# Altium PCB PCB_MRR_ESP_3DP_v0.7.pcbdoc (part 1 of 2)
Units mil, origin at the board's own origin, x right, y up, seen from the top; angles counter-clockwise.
Board outline 5100 x 5040 mil, 2 copper layers (Top Layer, Bottom Layer); 131 components, 154 nets, 480 pads, 79 vias.
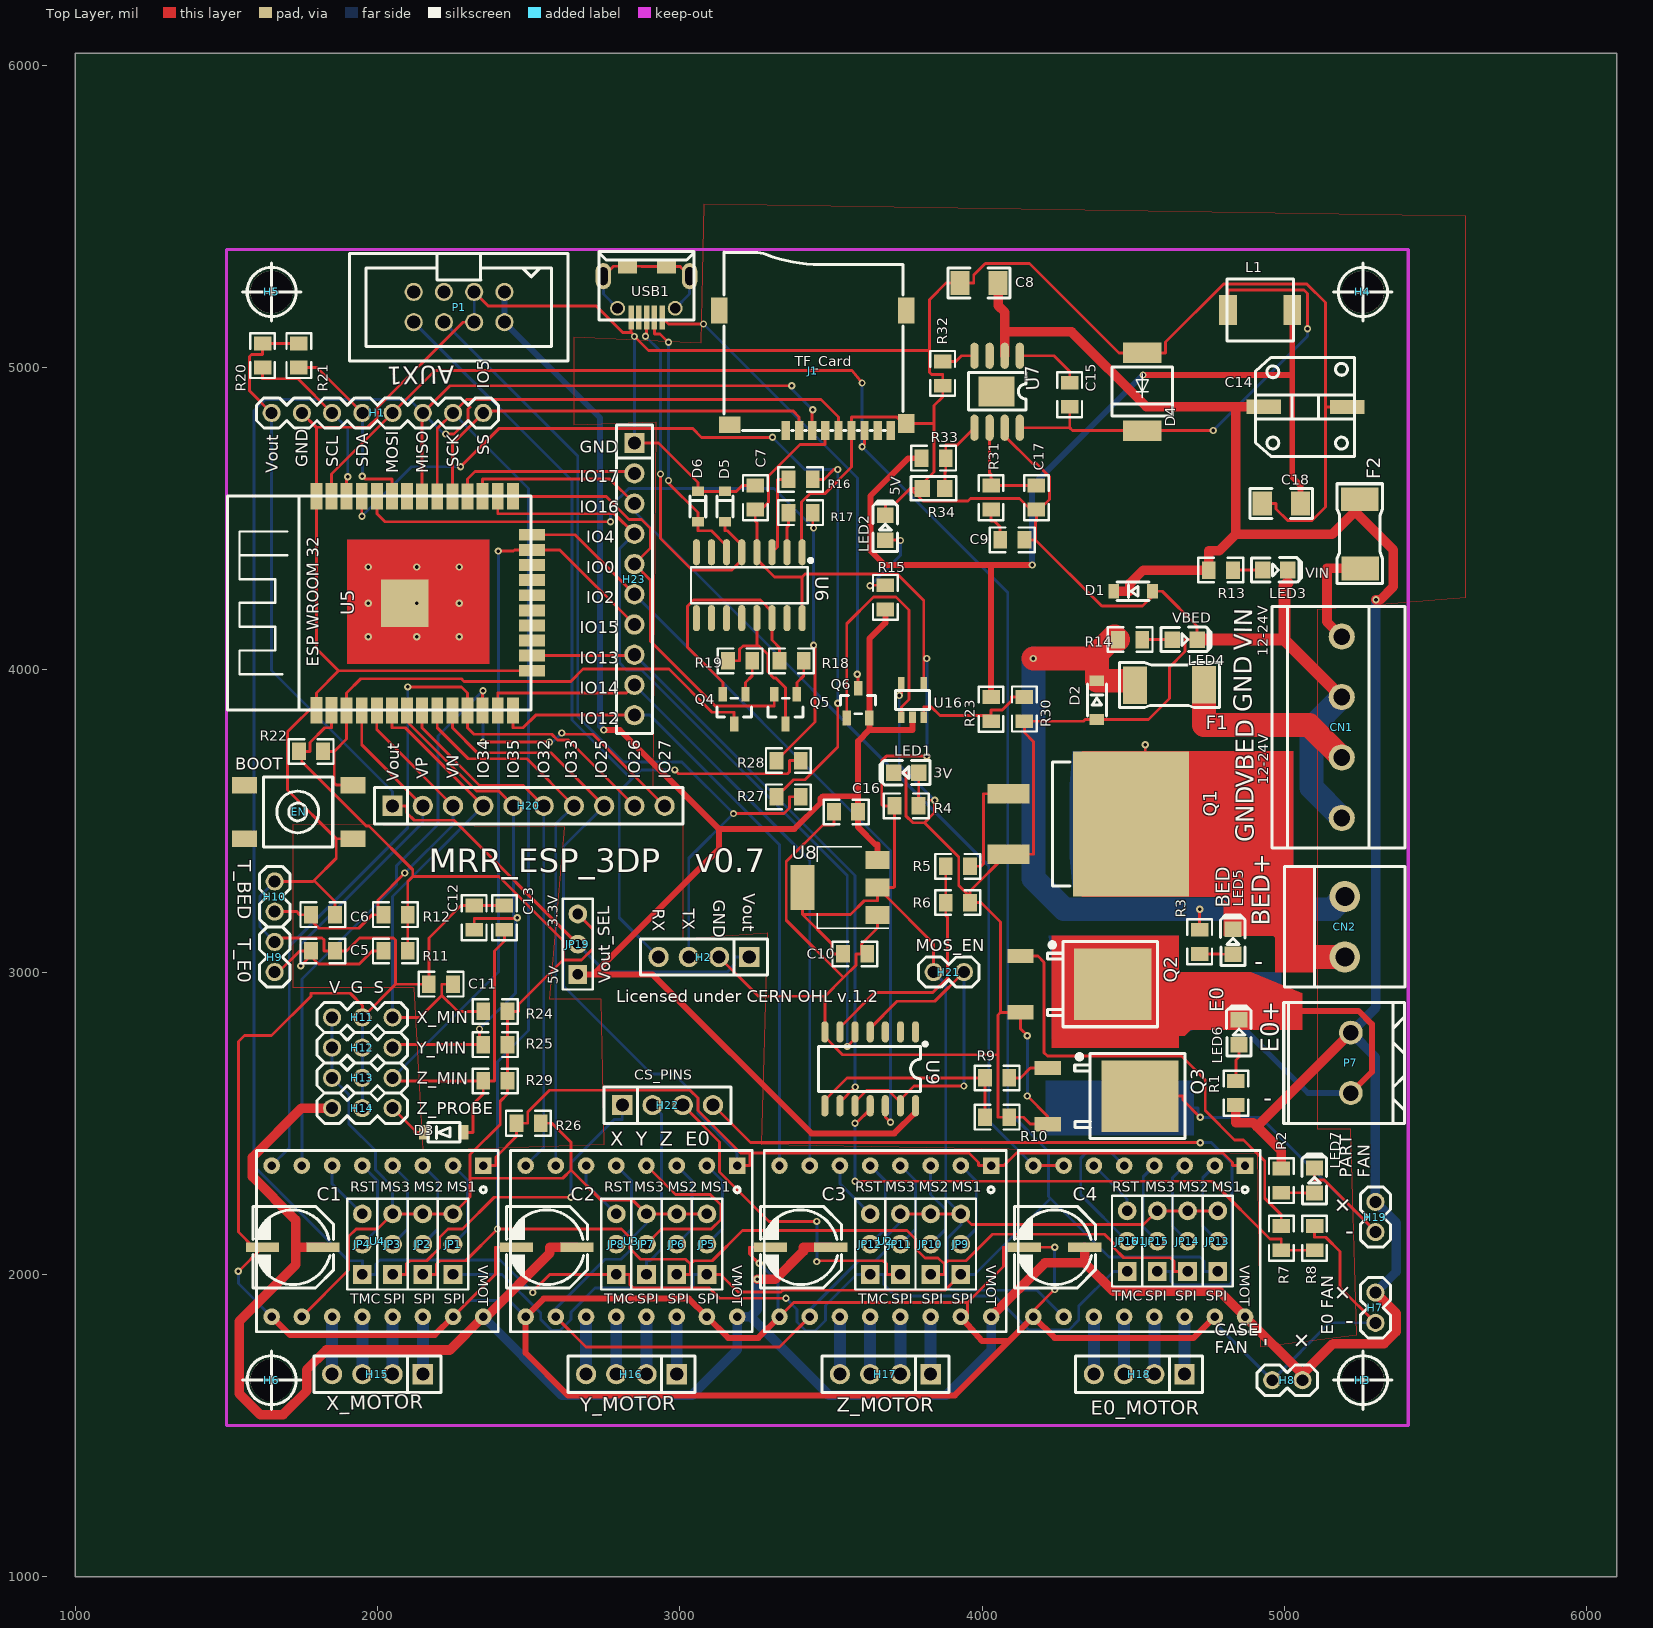
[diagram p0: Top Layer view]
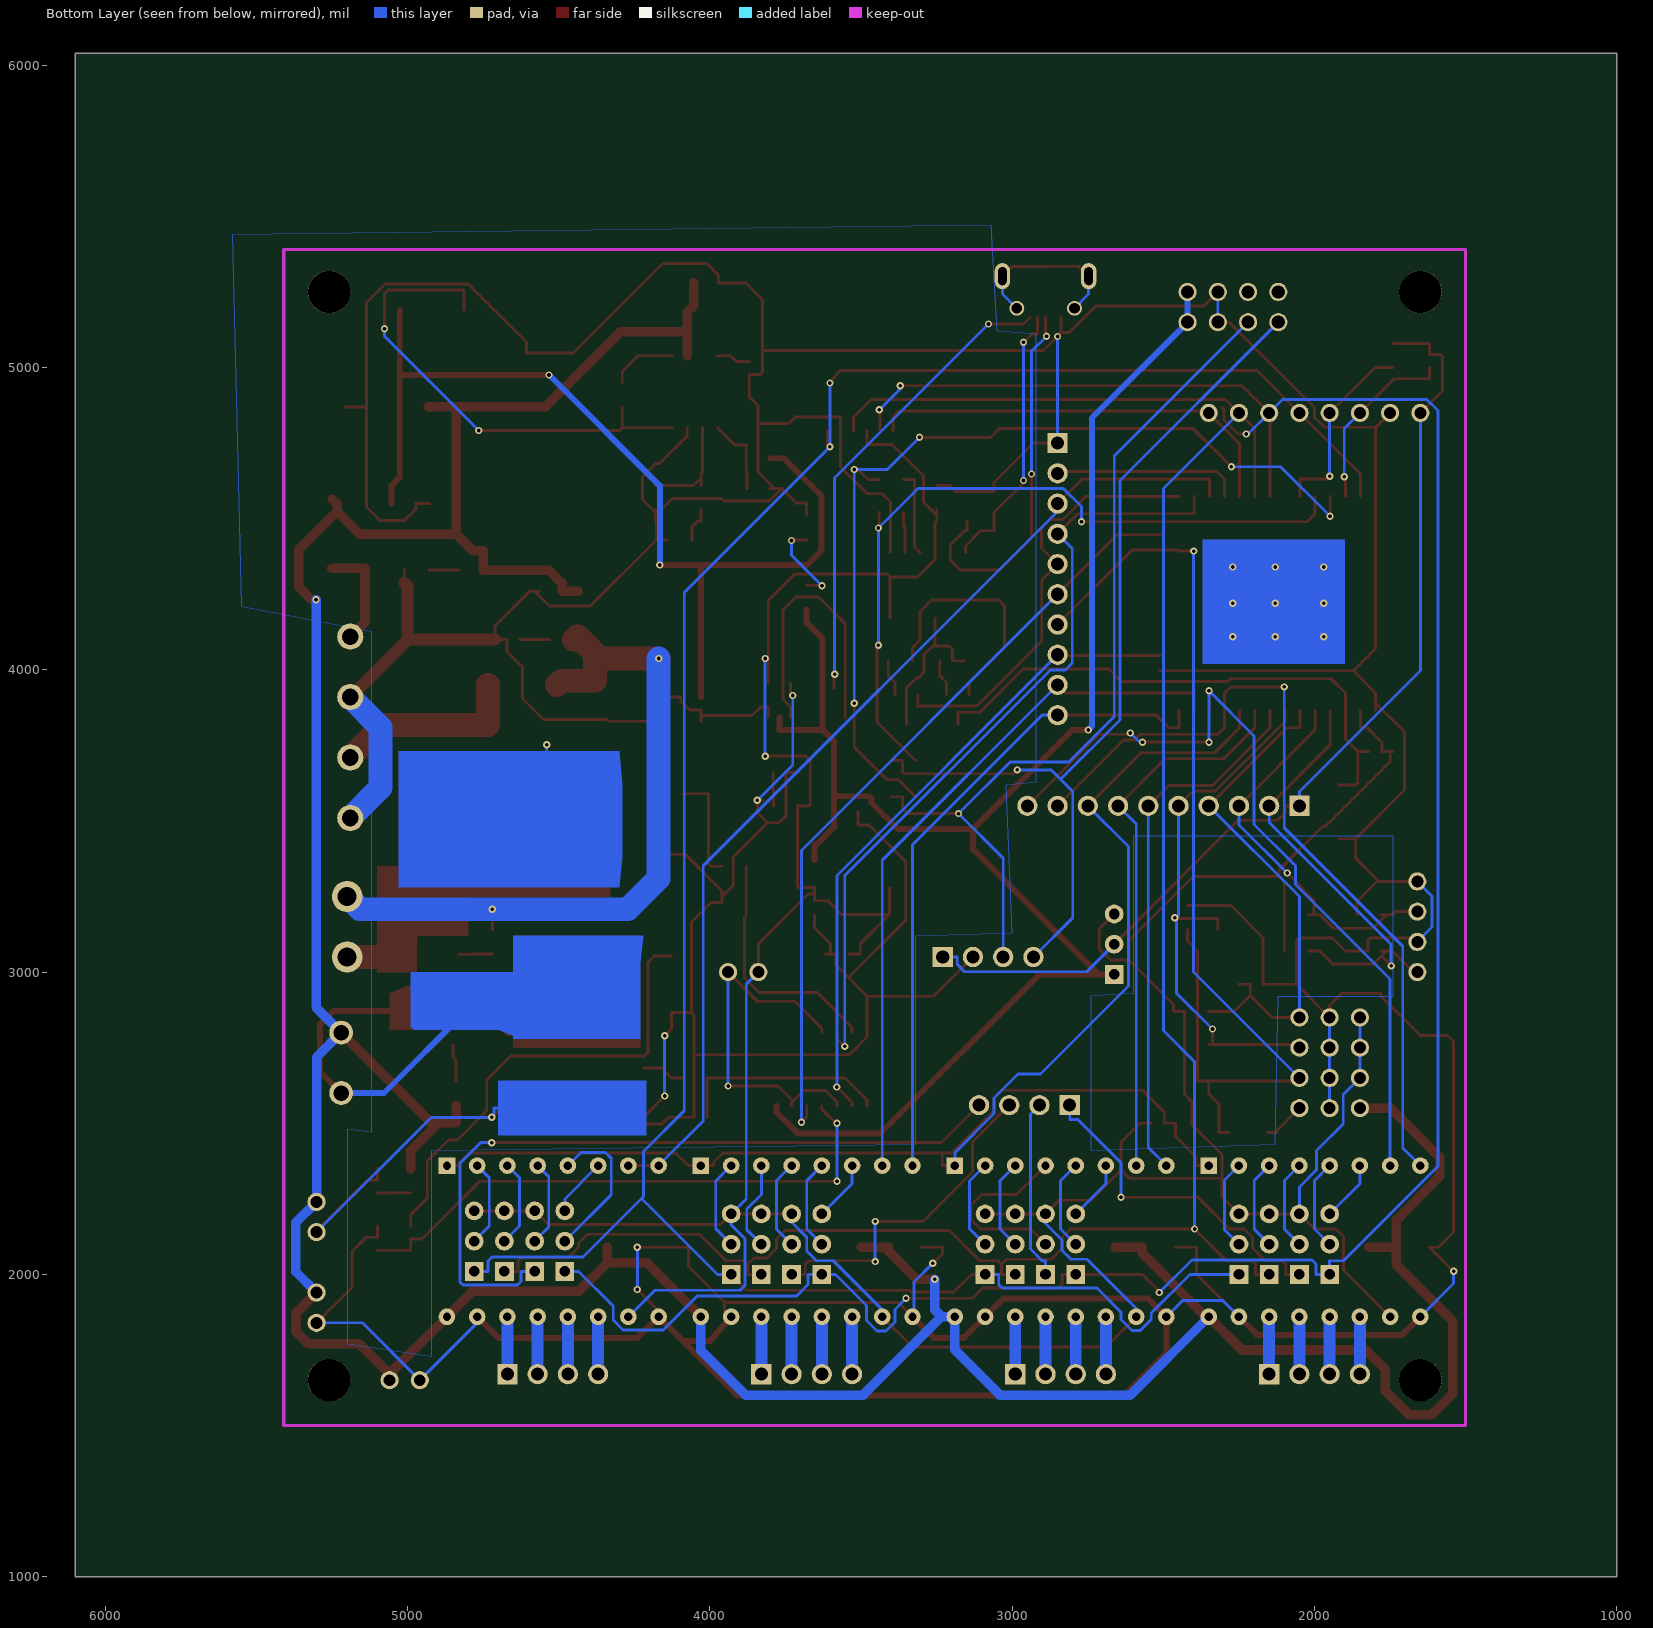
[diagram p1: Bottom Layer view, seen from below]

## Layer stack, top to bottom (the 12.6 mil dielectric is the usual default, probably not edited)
Top Layer: signal copper (thickness not stored)
Dielectric: dielectric 12.6, FR-4, Dk 4.8
Bottom Layer: signal copper (thickness not stored)

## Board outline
6100,1000 1000,1000 1000,6040 6100,6040

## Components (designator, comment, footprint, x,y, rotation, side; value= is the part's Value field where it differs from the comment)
C1 "100uF" CAP-D6.3XH7.7 1720,2090 r0 top
C2 "100uF" CAP-D6.3XH7.7 2560,2090 r0 top
C3 "100uF" CAP-D6.3XH7.7 3400,2090 r0 top
C4 "100uF" CAP-D6.3XH7.7 4240,2090 r0 top
C5 "10uF" 0805#1 1820,3070 r0 top
C6 "10uF" 0805#1 1820,3190 r0 top
C7 "1nF" 0805#1 3250,4570 r90 top
C8 "4.7uF" 1206 3990,5280 r180 top
C9 "820pF" 0805#1 4100,4430 r0 top
C10 "10uF" 0805#1 3580,3060 r0 top
C11 "100nF" 0805#1 2210,2960 r180 top
C12 "100nF" 0805#1 2320,3180 r90 top
C13 "100nF" 0805#1 2420,3180 r90 top
C14 "100uF" CAP-T-8*10 5070,4870 r0 top
C15 "100nF" 0805#1 4290,4910 r270 top
C16 "10uF" 0805#1 3550,3530 r180 top
C17 "56pF" 0805#1 4180,4570 r90 top
C18 "47uF" 1206 4990,4550 r0 top
CN1 "MKDS3/4-5.08" MKDS3/4-5.08 5190,3810 r90 top
CN2 "HEATBED" MKDS3/2-5.08 5200,3150 r0 top
D1 "1N4007" SOD-123F 4500,4260 r180 top
D2 "1N4007" SOD-123F 4380,3900 r90 top
D3 "1N4148W" SOD-123FL 2220,2470 r180 top
D4 "B540C-13-F" SMC(DO-214AB) 4530,4920 r270 top
D5 "PESD5V0S1BA" SOD-323 3150,4540 r90 top
D6 "PESD5V0S1BA" SOD-323 3060,4540 r90 top
EN "SWITCH,6*6*2.5,SMD" KEY-6.0*6.0 1740,3530 r0 top
F1 "0451020.MRL" SMF_045X 4620,3950 r180 top
F2 "0451003.MRL" SMF_045X 5250,4450 r90 top
H1 "I2C/SPI" 210S-1X8P 2000,4850 r0 top
H2 "Serial" DIP-1X4P-2.54MM-M 3080,3050 r180 top
H3 "HOLE" HOLE_3MM5 5260,1650 r0 top
H4 "HOLE" HOLE_3MM5 5260,5250 r0 top
H5 "HOLE" HOLE_3MM5 1650,5250 r0 top
H6 "HOLE" HOLE_3MM5 1650,1650 r0 top
H7 "FAN_HEATSINK" 210S-1X2P 5301.5,1889.9 r270 top
H8 "FAN_CASE" 210S-1X2P 5010,1650 r180 top
H9 "T_E0" 210S-1X2P 1660,3050 r90 top
H10 "T_BED" 210S-1X2P 1660,3250 r90 top
H11 "X_MIN" 210S-1X3P 1950,2850 r0 top
H12 "Y_MIN" 210S-1X3P 1950,2750 r0 top
H13 "Z_MIN" 210S-1X3P 1950,2650 r0 top
H14 "Z_PROBE" 210S-1X3P 1950,2550 r0 top
H15 "X_MOTOR" DIP-1X4P-2.54MM-M 2000,1670 r180 top
H16 "Y_MOTOR" DIP-1X4P-2.54MM-M 2840,1670 r180 top
H17 "Z_MOTOR" DIP-1X4P-2.54MM-M 3680,1670 r180 top
H18 "E0_MOTOR" DIP-1X4P-2.54MM-M 4520,1670 r180 top
H19 "FAN_E0" 210S-1X2P 5301.5,2189.9 r270 top
H20 "ESP_PINS1" DIP-1X10P-2.54MM-M 2500,3550 r0 top
H21 "MOSFET_ENABLE" 210S-1X2P 3890,3000 r0 top
H22 "CS_PINS" DIP-1X4P-2.54MM-M 2960,2560 r0 top
H23 "ESP_PINS2" DIP-1X10P-2.54MM-M 2850,4300 r270 top
J1 "Micro SD Card Holder" MICRO-SD9+4P-SMD-16.1X14.5X1.85MM 3440,4990 r90 top
JP1 "JP_X_MS1" HDR-3X1/2.54 2250,2100 r90 top
JP2 "JP_X_MS2" HDR-3X1/2.54 2150,2100 r90 top
JP3 "JP_X_MS3" HDR-3X1/2.54 2050,2100 r90 top
JP4 "JP_X_RST" HDR-3X1/2.54 1950,2100 r90 top
JP5 "JP_Y_MS1" HDR-3X1/2.54 3090,2100 r90 top
JP6 "JP_Y_MS2" HDR-3X1/2.54 2990,2100 r90 top
JP7 "JP_Y_MS3" HDR-3X1/2.54 2890,2100 r90 top
JP8 "JP_Y_RST" HDR-3X1/2.54 2790,2100 r90 top
JP9 "JP_Z_MS1" HDR-3X1/2.54 3930,2100 r90 top
JP10 "JP_Z_MS2" HDR-3X1/2.54 3830,2100 r90 top
JP11 "JP_Z_MS3" HDR-3X1/2.54 3730,2100 r90 top
JP12 "JP_Z_RST" HDR-3X1/2.54 3630,2100 r90 top
JP13 "JP_E0_MS1" HDR-3X1/2.54 4780,2110 r90 top
JP14 "JP_E0_MS2" HDR-3X1/2.54 4680,2110 r90 top
JP15 "JP_E0_MS3" HDR-3X1/2.54 4580,2110 r90 top
JP16 "JP_E0_RST" HDR-3X1/2.54 4480,2110 r90 top
JP19 "Vout_SEL" HDR-3X1/2.54 2662.8,3092.4 r90 top
L1 "4.7uH" 0530 4920,5190 r0 top
LED1 "LED_3V" LED-0805#1 3750,3660 r0 top
LED2 "LED_5V" LED-0805#1 3680,4470 r270 top
LED3 "LED_VIN" LED-0805#2 4970,4330 r180 top
LED4 "LED_VBED" LED-0805#2 4670,4100 r180 top
LED5 "BED" LED-0805#1 4830,3100 r270 top
LED6 "E0" LED-0805#1 4850,2800 r270 top
LED7 "FAN_E0" LED-0805#1 5100,2310 r270 top
P1 "AUX1" HDR-IDC-2.54-2X4P 2270,5200 r180 top
P7 "HOTEND_E0" WJ500V-5.08-2P 5220,2700 r90 top
Q1 "IRLS3034PBF" D2PAK 4290,3490 r270 top
Q2 "IRLR8743TRPBF" TO-252-2 4280,2960 r270 top
Q3 "IRLR8743TRPBF" TO-252-2 4370,2590 r270 top
Q4 "S9014" SOT-23(SOT-23-3) 3180,3870 r180 top
Q5 "S9014" SOT-23(SOT-23-3) 3350,3870 r180 top
Q6 "FDN340P" SOT-23(SOT-23-3) 3590,3890 r0 top
R1 "1.5KΩ(152)" 0805#1 4840,2600 r90 top
R2 "1.5KΩ(152)" 0805#1 4990,2310 r270 top
R3 "1.5KΩ(152)" 0805#1 4720,3100 r270 top
R4 "220Ω(221)" 0805#1 3750,3550 r0 top
R5 "10Ω(10R)" 0805#1 3920,3350 r0 top
R6 "100K" 0805#1 3920,3230 r0 top
R7 "10Ω(10R)" 0805#1 4990,2120 r90 top
R8 "100K" 0805#1 5100,2120 r90 top
R9 "10Ω(10R)" 0805#2 4050,2650 r0 top
R10 "100K" 0805#2 4050,2520 r0 top
R11 "4.7KΩ(472)" 0805#1 2060.01,3069.99 r0 top
R12 "4.7KΩ(472)" 0805#1 2060.01,3189.99 r0 top
R13 "2.2K" 0805#1 4790.01,4329.99 r0 top
R14 "2.2K" 0805#1 4490.01,4099.99 r0 top
R15 "330Ω(331)" 0805#1 3680,4240 r90 top
R16 "0Ω" 0805#1 3400,4630 r0 top
R17 "0Ω" 0805#1 3400,4520 r0 top
R18 "12KΩ(123)" 0805#1 3370,4030 r0 top
R19 "12KΩ(123)" 0805#1 3200,4030 r0 top
R20 "4.7KΩ(472)" 0805#1 1620,5040 r90 top
R21 "4.7KΩ(472)" 0805#1 1740,5040 r90 top
R22 "12KΩ(123)" 0805#1 1780,3730 r180 top
R23 "10KΩ" 0805#1 4030,3870 r90 top
R24 "10KΩ" 0805#1 2390,2870 r0 top
R25 "10KΩ" 0805#1 2390,2760 r0 top
R26 "10KΩ" 0805#1 2500,2500 r0 top
R27 "1KΩ" 0805#1 3360,3580 r0 top
R28 "1KΩ" 0805#1 3360,3700 r0 top
R29 "10KΩ" 0805#1 2390,2640 r0 top
R30 "47KΩ(473)" 0805#1 4140,3870 r270 top
R31 "23.7K" 0805#1 4030,4570 r90 top
R32 "73.2K" 0805#1 3870,4980 r270 top
R33 "60.4K" 0805#1 3840,4700 r0 top
R34 "11.5K" R0805 3840,4600 r180 top
U1 "POLULU_DRIVER" POLULU_DRIVER 4870,2360 r180 top
U2 "POLULU_DRIVER" POLULU_DRIVER 4030,2360 r180 top
U3 "POLULU_DRIVER" POLULU_DRIVER 3190,2360 r180 top
U4 "POLULU_DRIVER" POLULU_DRIVER 2350,2360 r180 top
U5 "ESP32-WROOM" ESP32_WROOM_FOOTPRINT 2090,4220 r90 top
U6 "CH340C" SOP-16_150MIL 3230,4280 r270 top
U7 "TPS54340DDAR" SOIC-8_150MIL-EP 4050,4920 r270 top
U8 "AMS1117-3.3" SOT-223 3530,3280 r180 top
U9 "74HCT126D" SOIC-14_150MIL 3630,2680 r270 top
U16 "MCP6001RT-I/OT" SOT-23-5 3770,3900 r0 top
USB1 "micro USBFemale" MICRO-USB-1 2890,5250 r90 top

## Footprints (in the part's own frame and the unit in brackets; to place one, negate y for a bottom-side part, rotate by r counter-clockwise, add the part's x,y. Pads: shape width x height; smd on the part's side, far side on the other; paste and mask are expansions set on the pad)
210S-1X2P [mil]
  round 60 hole 39.37: 1(-50,0) 2(50,0)
  silkscreen extent -100,-50 100,50
210S-1X3P [mil]
  round 60 hole 39.37: 1(-100,0) 2(0,0) 3(100,0)
  silkscreen extent -150,-50 150,50
210S-1X8P [mil]
  round 60 hole 39.37: 1(-350,0) 2(-250,0) 3(-150,0) 4(-50,0) 5(50,0) 6(150,0) 7(250,0) 8(350,0)
  silkscreen extent -400,-50 400,50
0530 [mm]
  rect 1.5x2.5 smd: 1(-2.7,0) 2(2.7,0)
  silkscreen extent -2.8,-2.6 2.8,2.6
0805#1 [mil]
  rect 45.67x57.87 smd: 1(-40,0) 2(40,0)
  silkscreen extent -75,-41 74,41
0805#2 [mil]
  rect 45.67x57.87 smd: 1(-40.05,0) 2(39.95,0)
  silkscreen extent -75,-41 74,41
1206 [mil]
  rect 63x78.74 smd: 1(-62.99,0) 2(62.99,0)
  silkscreen extent -103,-50 103,50
CAP-D6.3XH7.7 [mm]
  rect 2.8x0.8 smd: 1(2.54,0) 2(-2.54,0)
  silkscreen extent -3.37,-3.43 3.43,3.43
CAP-T-8*10 [mm]
  rect 2.9x1.2 smd: 1(-3.5,0.005) 2(3.5,-0.005)
  silkscreen extent -4.21,-4.16 4.1,4.15
D2PAK [mil]
  rect 63x137.8 smd: 1(-100,-202.5) 3(100,-202.5)
  rect 480.3x383.9 smd: 2(0.05,202.55)
  silkscreen extent -205,-57 205,2
DIP-1X4P-2.54MM-M [mm]
  rect 1.7x1.7 hole 1.1: 1(-3.81,0)
  round 1.7 hole 1.1: 2(-1.27,0) 3(1.27,0) 4(3.81,0)
  silkscreen extent -5.33,-1.52 5.33,1.52
DIP-1X10P-2.54MM-M [mm]
  rect 1.7x1.7 hole 1.1: 1(-11.43,0)
  round 1.7 hole 1.1: 2(-8.89,0) 3(-6.35,0) 4(-3.81,0) 5(-1.27,0) 6(1.27,0) 7(3.81,0) 8(6.35,0) 9(8.89,0) 10(11.43,0)
  silkscreen extent -12.95,-1.52 12.95,1.52
ESP32_WROOM_FOOTPRINT [mm]
  rect 2.2x1 smd: 1(-8.989,7.423) 2(-8.992,6.147) 3(-8.994,4.879) 4(-8.994,3.609) 5(-8.994,2.339) 6(-8.994,1.069) 7(-8.994,-0.201) 8(-8.997,-1.468) 9(-8.997,-2.738) 10(-8.997,-4.008) 11(-8.997,-5.278) 12(-8.994,-6.551) 13(-8.994,-7.821) 14(-8.994,-9.091) 25(8.992,-9.093) 26(8.992,-7.823) 27(8.992,-6.553) 28(8.989,-5.281) 29(8.989,-4.011) 30(8.989,-2.741) 31(8.989,-1.471) 32(8.992,-0.203) 33(8.992,1.067) 34(8.992,2.337) 35(8.992,3.607) 36(8.992,4.877) 37(8.994,6.144) 38(8.997,7.421)
  rect 1x2.2 smd: 15(-5.667,-10.693) 16(-4.397,-10.693) 17(-3.127,-10.693) 18(-1.859,-10.696) 19(-0.589,-10.696) 20(0.681,-10.696) 21(1.951,-10.696) 22(3.223,-10.693) 23(4.493,-10.693) 24(5.763,-10.693)
  rect 4x4 smd: 39(-0.001,-0.011)
  silkscreen extent -8.97,-10.63 9.03,14.87
HDR-3X1/2.54 [mil]
  rect 62x62 hole 35: 1(-100,0)
  round 62 hole 35: 2(0,0) 3(100,0)
  silkscreen extent -150,-50 150,50
HDR-IDC-2.54-2X4P [mil]
  round 60 hole 43.3: 1(-150,-50) 2(-150,50) 3(-50,-50) 4(-50,50) 5(50,-50) 6(50,50) 7(150,-50) 8(150,50)
  silkscreen extent -361,-177 362,178
HOLE_3MM5 [mil]
  round 140 hole 140: 1(0,0)
  silkscreen extent -96,-96 96,96
KEY-6.0*6.0 [mm]
  rect 2.1x1.4 smd: 1(4.55,-2.252) 2(-4.553,-2.252) 3(4.553,2.252) 4(-4.553,2.249)
  silkscreen extent -2.95,-2.95 2.85,2.95
LED-0805#1 [mil]
  rect 51.2x55.1 smd: 1(40.7,0.05) 2(-42,0.05)
  silkscreen extent -88,-41 78,40
LED-0805#2 [mil]
  rect 51.2x55.1 smd: 1(41.4,-0.05) 2(-41.3,-0.05)
  silkscreen extent -88,-41 78,40
MICRO-SD9+4P-SMD-16.1X14.5X1.85MM [mil]
  rect 63x27.6 smd: 1(-199,89) 2(-199,45) 3(-199,2) 4(-199,-41) 5(-199,-85) 6(-199,-128) 7(-199,-171) 8(-199,-215) 9(-199,-258)
  rect 63x55.1 smd: G1(-175,-309.05)
  rect 86.6x55.1 smd: G2(199,-309.05) G3(199,308.95)
  rect 55.1x70.9 smd: G4(-179.05,273.95)
  silkscreen extent -199,-298 392,293
MICRO-USB-1 [mm]
  round 1.25 hole 0.9: 0(-1.371,2.431) 0(-1.371,-2.41)
  oval 2.2x1.3 hole 0.7 slot 1.5 at 0 deg: 0(1.329,3.619) 0(1.329,-3.619)
  rect 1.2x1.6 smd: 0(2.14,-1.684) 0(2.156,1.595)
  rect 2x0.45 smd: 1(-2.156,-1.311) 2(-2.156,-0.66) 3(-2.156,-0.011) 4(-2.156,0.639) 5(-2.156,1.289)
  silkscreen extent -2.36,-4 3.4,4
MKDS3/2-5.08 [mm]
  round 2.6 hole 1.6: 1(0,-2.54) 2(0,2.54)
  silkscreen extent -5.08,-5.08 5.08,5.08
MKDS3/4-5.08 [mm]
  round 2.2 hole 1.4: 1(-7.62,0) 2(-2.54,0) 3(2.54,0) 4(7.62,0)
  silkscreen extent -10.16,-5.33 10.16,5.84
POLULU_DRIVER [mil]
  rect 55x55 hole 28: 1(0,0)
  round 55 hole 28: 2(100,0) 3(200,0) 4(300,0) 5(400,0) 6(500,0) 7(600,0) 8(700,0) 9(700,500) 10(600,500) 11(500,500) 12(400,500) 13(300,500) 14(200,500) 15(100,500) 16(0,500)
  silkscreen extent -50,-50 750,550
R0805 [mil]
  rect 51.2x55.1 smd: 1(-37.4,0) 2(37.4,0)
  silkscreen extent -75,-39 75,39
SMC(DO-214AB) [mil]
  rect 67.87x126 smd: 1(-128.4,0) 2(128.4,0)
  silkscreen extent -82,-100 81,100
SMF_045X [mil]
  rect 78.74x124.02 smd: 1(-114.35,-0.5) 2(114.35,0.5)
  silkscreen extent -165,-74 166,75
SOD-123F [mil]
  rect 35.8x48 smd: 1(-64,0) 2(64,0)
  silkscreen extent -53,-31 53,31
SOD-123FL [mil]
  rect 35.8x48 smd: 1(64,0) 2(-64,0)
  silkscreen extent -53,-32 53,32
SOD-323 [mm]
  rect 0.8x1 smd: 1(-1.269,0) 2(1.271,0)
  silkscreen extent -0.89,-0.66 0.89,0.66
SOIC-8_150MIL-EP [mm]
  oval 2.2x0.7 smd: 1(-3.023,1.905) 2(-3.023,0.635) 3(-3.023,-0.635) 4(-3.023,-1.905) 5(3.023,-1.905) 6(3.023,-0.635) 7(3.023,0.635) 8(3.023,1.905)
  rect 2.5x3 smd: 9(-0.025,-0.051)
  silkscreen extent -1.6,-2.41 1.55,2.41
SOIC-14_150MIL [mm]
  oval 1.8x0.6 smd: 1(-3.099,3.81) 2(-3.099,2.54) 3(-3.099,1.27) 4(-3.099,0) 5(-3.099,-1.27) 6(-3.099,-2.54) 7(-3.099,-3.81) 8(3.099,-3.81) 9(3.099,-2.54) 10(3.099,-1.27) 11(3.099,0) 12(3.099,1.27) 13(3.099,2.54) 14(3.099,3.81)
  silkscreen extent -2.23,-4.34 1.91,4.77
SOP-16_150MIL [mm]
  oval 2.2x0.6 smd: 1(-2.769,4.445) 2(-2.769,3.175) 3(-2.769,1.905) 4(-2.769,0.635) 5(-2.769,-0.635) 6(-2.769,-1.905) 7(-2.769,-3.175) 8(-2.769,-4.445) 9(2.769,-4.445) 10(2.769,-3.175) 11(2.769,-1.905) 12(2.769,-0.635) 13(2.769,0.635) 14(2.769,1.905) 15(2.769,3.175) 16(2.769,4.445)
  silkscreen extent -2.23,-4.9 1.52,5.3
SOT-23(SOT-23-3) [mm]
  rect 0.7x1.25 smd: 1(-0.95,-1.25) 2(0.95,-1.25) 3(0,1.25)
  silkscreen extent -1.46,-0.9 1.46,0.65
SOT-23-5 [mil]
  rect 21.7x39.37 smd: 1(-37,-57) 2(0,-57) 3(37,-57) 4(37,57) 5(-37,57)
  silkscreen extent -56,-32 56,32
SOT-223 [mm]
  rect 2x1.5 smd: 1(-3.15,2.3) 2(-3.15,0) 3(-3.15,-2.3)
  rect 2x3.8 smd: 4(3.15,0)
  silkscreen extent -4.1,-3.41 1.91,3.41
TO-252-2 [mm]
  rect 1.2x2.2 smd: 1(-2.362,-3.876) 3(2.362,-3.871)
  rect 6x6.5 smd: 4(0,3.877)
  silkscreen extent -3.57,-1.61 3.57,7.64
WJ500V-5.08-2P [mm]
  round 2 hole 1.3: 1(-2.54,0) 2(2.54,0)
  silkscreen extent -5.08,-4.52 5.08,5.64

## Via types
v1: diameter 24.02, hole 12.2, Top Layer to Bottom Layer, 62 vias
v2: diameter 24.4, hole 12, Top Layer to Bottom Layer, 17 vias

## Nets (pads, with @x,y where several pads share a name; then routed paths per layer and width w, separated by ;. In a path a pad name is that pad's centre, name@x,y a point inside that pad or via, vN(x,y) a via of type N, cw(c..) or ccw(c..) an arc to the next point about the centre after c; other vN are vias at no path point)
5V1: C18.2 L1.2 R23.2 R33.1 | length 3318.8
  Top Layer w19.68: R33.1@3800,4700 3755.5,4700 3630.8,4575.3 3630.8,4394.7 3678.7,4346.8 4030,4346.8 ; R23.2@4030,3909.99 4030,4346.8 ; v1(4166,4346.8) 4030,4346.8 ; v1(4532.4,4975.6) 5026.3,4975.6 ; L1.2@5026.3,5190 5026.3,4975.6 ; C18.2@5052.99,4550 5053,4611 5026.3,4637.7 5026.3,4975.6
  Bottom Layer w19.68: v1(4166,4346.8) 4166,4609.2 v1(4532.4,4975.6)
+3.3V: C7.1 C10.1 H11.1 H12.1 H13.1 H21.1 J1.4 JP1.3 JP2.3 JP3.3 JP5.3 JP6.3 JP7.3 JP9.3 JP10.3 JP11.3 JP13.3 JP14.3 JP15.3 JP19.3 R4.1 R11.2 R12.2 R22.2 R24.2 R25.2 R26.2 R29.2 U1.10 U2.10 U3.10 U4.10 U5.2 U6.4 U6.16 U8.2 U8.4 U16.4 | length 13555.3
  Top Layer w9.45: R22.2@1740,3730 R22.2@1749.4,3730 ; U4.10@1750,1860 1904.7,2014.7 1904.7,2124.9 1929.8,2150 2000,2150 JP3.3@2050,2200 JP2.3@2150,2200 JP1.3@2250,2200 2306.6,2256.6 2306.6,2318.2 ; U5.2@1848,3866 1848,3808.4 1825.8,3808.4 1777.1,3759.7 1777.1,3730 R22.2@1749.4,3730 ; R11.2@2100,3070 R12.2@2100,3190 2100,3300.1 2116.7,3316.7 ; R26.2@2540,2500 2577.1,2500 2640,2437.1 2640,2345.5 ; U3.10@2590,1860 2690,1760 3330,1760 U2.10@3430,1860 ; JP19.3@2662.8,3192.4 2712.3,3142.9 2712.3,3076.9 2675.3,3040 2613.8,3040 ; JP5.3@3090,2200 JP6.3@2990,2200 JP7.3@2890,2200 2844.7,2245.3 2740.2,2245.3 2640,2345.5 ; C7.1@3250,4530 C7.1@3250,4511.5 ; U6.16@3405,4171 3405,4307.5 ; U8.4@3406,3280 3406,3190.9 ; J1.4@3481,4791 3481,4745.2 3397.6,4745.2 3293.2,4640.8 3293.2,4554.6 C7.1@3250,4511.5 ; C10.1@3540,3060 3502.9,3060 3502.9,3094 3406,3190.9 ; JP11.3@3730,2200 JP10.3@3830,2200 JP9.3@3930,2200 3965.3,2164.7 4534.7,2164.7 JP15.3@4580,2210 JP14.3@4680,2210 JP13.3@4780,2210 ; U16.4@3807.1,3957 3807.1,3991 v1@3807.1,4037.4 ; v1(3817.5,3714.4) 3683.4,3714.4 3668.1,3699.1 3668.1,3554.9 3672.9,3550 R4.1@3709.99,3550.04 3710,3541.8 3710,3533.6 3710,3528.4 3710,3506.8 3710,3282.3 3707.7,3280 3657.7,3280 U8.2@3654,3280 U8.2@3654,3258.1 ; v1(3817.5,4037.4) v1@3807.1,4037.4 ; H21.1@3840,3000 3840,3093.6 3675.5,3258.1 U8.2@3654,3258.1 ; R22.2@1749.4,3730 1749.4,3696.8 1963,3483.2 1971.9,3483.2 2116.7,3338.5 2116.7,3316.7 ; 2116.7,3316.7 2401.7,3316.7 2613.8,3104.6 2613.8,3040 ; 2306.6,2318.2 2612.7,2318.2 2640,2345.5 ; 2306.6,2318.2 2306.6,2396.3 2406.1,2495.8 2406.1,2572.9 2430,2596.8 R29.2@2430,2640 R25.2@2430,2760 R24.2@2430,2870 2467.1,2870 2467.1,2893.3 2613.8,3040 ; C7.1@3250,4511.5 3250,4492.9 3255,4487.9 U6.4@3255,4389 3255,4365.6 3313.1,4307.5 3405,4307.5 ; 3405,4307.5 3414.5,4317.1 3719.5,4317.1 3807.1,4229.5 v1@3807.1,4037.4 ; 3406,3190.9 3564.9,3190.9 3610.2,3236.2 3654,3236.2 U8.2@3654,3258.1
  Bottom Layer w9.45: H11.1@1850,2850 H12.1@1850,2750 H13.1@1850,2650 1905.1,2594.9 1905.1,2497.6 1993.3,2409.5 1993.3,2346.3 2050,2289.6 JP3.3@2050,2200 ; U3.10@2590,1860 2590,1887.2 2752.8,2050 2806,2050 2835.3,2079.2 2835.3,2113.8 2890,2168.6 JP7.3@2890,2200 ; U2.10@3430,1860 3430,1882.9 3592.4,2045.3 3647.6,2045.3 3680,2077.6 3680,2123.1 3730,2173.1 JP11.3@3730,2200 ; v1(3817.5,3714.4) v1(3817.5,4037.4) ; H21.1@3840,3000 3880,2960 3880,2250 JP9.3@3930,2200 3930,2164 3884.7,2118.7 3884.7,1962.8 3899.9,1947.6 4182.4,1947.6 U1.10@4270,1860
+5V: C16.1 JP19.1 P1.1 P1.2 Q6.2 R15.1 U8.3 U9.14 U16.2 | length 5734.1
  Top Layer w19.68: JP19.1@2662.8,2992.4 2715.5,2992.4 ; v1(2748.9,3801.2) 2802,3801.2 3129.2,3474 ; U8.3@3654,3370.5 3654,3421.8 3647.7,3421.8 3590,3479.4 C16.1@3590.01,3529.99 3590,3581.8 ; R15.1@3680,4200 3680,4155.5 3627.4,4102.9 Q6.2@3627.4,3840.8 3627.4,3817.7 3627.4,3801.6 ; U16.2@3770.1,3843 3770.1,3801.6 3627.4,3801.6 ; U9.14@3780,2558 3780,2536.6 3709.7,2466.4 3435.7,2466.4 2909.6,2992.4 2715.5,2992.4 ; 2715.5,2992.4 3129.2,3406.1 3129.2,3474 ; 3129.2,3474 3379.8,3474 3465.5,3559.7 3465.5,3573.8 3473.5,3581.8 3590,3581.8 ; 3590,3581.8 3590,3764.2 3627.4,3801.6
  Bottom Layer w19.68: P1.1@2420,5250 P1.2@2420,5150 2736.8,4833.2 2736.8,3813.3 v1(2748.9,3801.2)
COMP: C17.2 R31.2 U7.6 | length 353.4
  Top Layer w9.45: U7.6@4025,4801 4025,4652.1 4030,4647.1 4030,4635 ; R31.2@4030,4610 4030,4635 ; C17.2@4180,4610 4055,4610 4030,4635
D3_1: D3.1 H14.3 | length 142.8
  Top Layer w9.45: H14.3@2050,2550 2123.8,2476.2 2123.8,2470 D3.1@2156,2470
DTR: Q5.3 R19.1 U6.13 | length 535.2
  Top Layer w9.45: R19.1@3160,4030 3197.1,4030 3197.1,4067.1 3209.3,4079.3 3255,4079.3 ; U6.13@3255,4171 3255,4079.3 ; Q5.3@3350,3820.8 3350,3940.6 3318.2,3972.4 3311.3,3972.4 3291.5,3992.3 3291.5,4050.4 3262.6,4079.3 3255,4079.3
E0_CS: H22.4 JP15.1 | length 2479.3
  Top Layer w9.45: H22.4@3110,2560 3234.1,2435.9 v1(4721.7,2435.9)
  Bottom Layer w9.45: JP15.1@4580,2010 4625.3,2010 4625.3,1976.1 4636.8,1964.5 4817,1964.5 4826.7,1974.2 4826.7,2367.6 4758.5,2435.9 v1(4721.7,2435.9)
E0_DIR_PIN: H23.2 U5.28 | length 622.5
  Top Layer w9.45: U5.28@2297.9,4573.9 2297.9,4631.5 2322.7,4656.2 2843.8,4656.2 H23.2@2850,4650
E0_MS1: JP13.2 U1.2 | length 287.3
  Bottom Layer w9.45: U1.2@4770,2360 4730,2320 4730,2160 JP13.2@4780,2110
E0_MS2: JP14.2 U1.3 | length 287.3
  Bottom Layer w9.45: U1.3@4670,2360 4630,2320 4630,2160 JP14.2@4680,2110
E0_MS3: JP15.2 U1.4 | length 284.6
  Bottom Layer w9.45: U1.4@4570,2360 4533.2,2323.2 4533.2,2156.8 JP15.2@4580,2110
E0_RST: JP16.2 U1.5 | length 506.9
  Bottom Layer w9.45: U1.5@4470,2360 4426.6,2403.4 4345.9,2403.4 4326.7,2384.2 4326.7,2263.3 JP16.2@4480,2110
E0_SLP: JP16.3 U1.6 | length 195.6
  Bottom Layer w9.45: U1.6@4370,2360 4480,2250 JP16.3@4480,2210
E0_STEP_PIN: H23.3 U1.7 U1.8 U5.27 | length 3430.2
  Top Layer w9.45: U5.27@2348,4574 2348,4631.6 2768.4,4631.6 H23.3@2850,4550 ; U1.8@4170,2360 U1.7@4270,2360
  Bottom Layer w9.45: H23.3@2850,4550 2850,4523.9 4022.3,3351.7 4022.3,2507.7 U1.8@4170,2360
EN: EN.3 Q4.3 R22.1 U5.3 | length 1837.4
  Top Layer w9.45: R22.1@1820,3730 1838.5,3730 1857.1,3730 ; EN.3@1919.3,3618.6 1863.6,3618.6 1857.1,3625.2 1857.1,3730 ; Q4.3@3180,3820.8 3180,3859.7 3107,3859.7 2964.4,4002.3 2680.1,4002.3 2639.4,3961.5 2286.6,3961.5 2277.7,3970.4 1944.8,3970.4 1897.9,3923.5 U5.3@1897.9,3865.9 1897.9,3837.1 1897.9,3808.3 1897.9,3770.8 1857.1,3730
EN_2: EN.2
EN_4: EN.4
F1_1: CN1.2 F1.1 | length 633.1
  Top Layer w78.74: F1.1@4734.35,3950.5 4734.4,3817.6 5082.4,3817.6 CN1.2@5190,3710
F2_1: CN1.4 F2.1 | length 355.1
  Top Layer w31.5: CN1.4@5190,4110 5141.2,4158.8 5141.2,4335.6 F2.1@5250.5,4335.65
FAN_E0_PIN: H23.8 U5.16 U9.9 | length 2155.5
  Top Layer w9.45: U5.16@2511,4046.9 2568.6,4046.9 2846.9,4046.9 H23.8@2850,4050 ; U9.9@3530,2558 3530,2569.6 v1(3580.2,2619.8)
  Bottom Layer w9.45: H23.8@2850,4050 3580.2,3319.8 v1(3580.2,2619.8)
FB: R33.2 R34.1 U7.5 | length 263.2
  Top Layer w9.45: R34.1@3877.4,4600 3877.4,4654.2 3880,4656.8 R33.2@3880,4700 3880,4743.2 3917.2,4743.2 U7.5@3975,4801
GND: C1.2 C2.2 C3.2 C4.2 C5.2 C6.2 C7.2 C8.2 C9.2 C10.2 C11.2 C12.2 C13.2 C14.2 C16.2 C17.1 C18.1 CN1.1 CN1.3 D1.1 D2.1 D4.1 D5.2 D6.2 EN.1 H1.2 H2.2 H7.2 H8.2 H9.2 H10.2 H11.2 H12.2 H13.2 H14.2 H23.1 J1.6 J1.G1 LED1.2 LED2.2 LED3.2 LED4.2 P1.3 P1.4 Q1.3 Q2.3 Q3.3 R6.2 R8.2 R10.2 R30.2 R32.2 R34.2 U1.9 U1.15 U2.9 U2.15 U3.9 U3.15 U4.9 U4.15 U5.1 U5.15 U5.38 U6.1 U7.7 U8.1 U9.7 U16.5 USB1.5 | length 30998.9
  Top Layer w9.45: v2(1540,2010) C1.2@1620,2090 1590,2090 1540,2140 1540,2770 1560,2790 1650,2790 1780,2920 1780,2930 1910,2930 1950,2890 H11.2@1950,2850 2060,2960 ; H9.2@1660,3100 1673.2,3113.2 1816.8,3113.2 1822.9,3107.1 1822.9,3070 C5.2@1860,3070 1897.1,3070 1940.2,3113.2 2052.9,3113.2 2060,3106.1 2060,2960 ; H10.2@1660,3300 1787.1,3300 1790.1,3303 ; H1.2@1750,4850 1797.6,4802.4 1797.9,4802.4 ; U5.1@1797.75,3866.1 U5.1@1797.8,3890.1 ; C6.2@1860,3190 1860,3233.2 1790.1,3303 ; EN.1@1919.2,3441.3 1863.5,3441.3 ; U4.15@2250,1860 2390.6,2000.6 2390.6,2090 C2.2@2460,2090 ; P1.4@2320,5150 2282.6,5150 2000,4867.4 2000,4835.3 1967,4802.4 1797.9,4802.4 ; P1.3@2320,5250 2366.6,5203.4 2724,5203.4 2811.2,5116.2 2839.3,5116.2 ; C13.2@2420,3220 C12.2@2320,3220 2276.8,3220 2170,3113.2 C11.2@2170,2960 2060,2960 ; U5.15@2511,3996.9 1871,3996.9 ; USB1.5@2839.3,5165.1 2839.3,5116.2 ; H23.1@2850,4750 2930.1,4750 3060,4620.1 D6.2@3060,4590.05 D5.2@3150,4590.05 3186.9,4590 3206.8,4610 C7.2@3250,4610 ; H2.2@3130,3050 3260,2920 3480,2920 ; v1(3263,2037) 3261.1,2037 3230.6,2067.5 3230.6,2090 C3.2@3300,2090 ; U2.9@3330,1860 3377,1907 3951.8,1907 ; U6.1@3405,4389 3402.9,4391.1 3402.9,4555.1 3430.4,4582.6 3479.8,4582.6 3568,4670.8 3568,4745.2 J1.6@3568,4791 3568,4813.9 3568,4836.8 3717.7,4836.8 3739.5,4815 3749.1,4815 3790.9,4815 3841.2,4815 ; C16.2@3510.01,3529.99 3510,3486.8 3473.8,3486.8 3352.3,3365.4 3352.3,3171.6 3542,2982 ; C10.2@3620,3060 C10.2@3601.5,3060 ; U8.1@3654,3189.45 3654,3145.6 3601.5,3093.1 C10.2@3601.5,3060 ; LED2.2@3680.1,4512 3680.1,4551.9 3714.6,4551.9 3762.7,4600 ; LED1.2@3708,3660.05 3747.9,3660 3747.9,3517.4 3771.2,3494.1 3809.3,3494.1 ; v1(3726.3,3915.2) 3733.1,3922 U16.5@3733.1,3957 ; R34.2@3802.6,4600 R34.2@3786.4,4600 ; 3823.6,3568.4 v1(3843.3,3568.4) 3843.3,3528.2 3809.3,3494.1 ; U2.15@3930,1860 3950,1860 3951.8,1861.8 3951.8,1907 ; U7.7@4075,4801 4075,4774.1 4166.6,4682.5 4179.7,4682.5 4223.2,4639 4223.2,4563.9 C17.1@4180,4520.7 ; C9.2@4140,4430 4177.1,4430 ; v2(4150,2590) 4217.6,2522.4 Q3.3@4217.6,2497 4160,2497 4137,2520 R10.2@4089.95,2520 4052.8,2520 4052.8,2726.7 ; v2(4150,2790) 4127.6,2812.4 Q2.3@4127.6,2867 4070,2867 4061.4,2867 ; U1.9@4170,1860 4170,1880 v2(4240,1950) ; C17.1@4180,4530 C17.1@4180,4520.7 ; v2(4240,2090) C4.2@4140,2090 4070.6,2090 4070.6,2025.8 3951.8,1907 ; D1.1@4564,4260 D1.1@4580.1,4260 ; C18.1@4927.01,4550 4972.8,4550 4972.8,4532.6 5011.3,4494 5091.9,4494 5136.4,4538.5 5136.4,4869.8 ; 5011.3,4288.2 LED3.2@5011.3,4330.05 ; R8.2@5100,2159.9 5100,2122.8 5137.1,2122.8 5184.3,2075.7 5184.3,1957.1 H7.2@5301.5,1839.9 ; C14.2@5207.8,4869.8 5136.4,4869.8 ; 1790.1,3303 1863.5,3376.5 1863.5,3441.3 ; U5.1@1797.8,3890.1 1702.6,3794.9 1702.6,3602.3 1863.5,3441.3 ; U5.1@1797.8,3890.1 1797.8,3923.7 1871,3996.9 ; 1797.9,4802.4 1797.9,4631.8 1797.9,4574.2 1797.9,4070 1871,3996.9 ; 2839.3,5116.2 2850,5105.4 v1(2850,5102.9) 2896.8,5056.1 3826.8,5056.1 ; 3480,2920 U9.7@3480,2802 3480,2785.3 3538.6,2726.7 4052.8,2726.7 ; 3480,2920 3542,2982 ; 3542,2982 3582.9,3022.9 3582.9,3060 C10.2@3601.5,3060 ; 3762.7,4600 3804.6,4558.2 3953.3,4558.2 3962.2,4567.1 4124.3,4567.1 C17.1@4180,4511.4 ; 3762.7,4600 R34.2@3786.4,4600 ; R34.2@3786.4,4600 3841.2,4654.8 3841.2,4815 ; 3809.3,3494.1 3922.9,3380.4 3922.9,3286.3 R6.2@3960,3249.2 ; 3826.8,5056.1 3826.8,4983.2 3832.9,4977.1 3870,4977.1 R32.2@3870,4940 3870,4902.9 3841.2,4874.1 3841.2,4815 ; 3826.8,5056.1 3826.8,5225.5 3881.3,5280 C8.2@3927.01,5280 3972.8,5280 3972.8,5305.7 4010.9,5343.8 4157.3,5343.8 4452.7,5048.4 D4.1@4530,5048.4 4607.3,5048.4 4607.3,5084.5 4799.6,5276.9 5074.4,5276.9 5136.4,5214.9 5136.4,4869.8 ; R6.2@3960,3249.2 3960,3268.4 4081.6,3390 Q1.3@4087.5,3390 4170.7,3390 4170.7,3762.3 4140,3792.9 R30.2@4140.01,3830 4335.7,3830 4341.7,3836 D2.1@4380,3836 4550.8,3836 4620,3905.1 4620,4008.7 4671.4,4060.2 4671.4,4100 LED4.2@4711.3,4100.05 4711.3,4144.9 4596.2,4260 D1.1@4580.1,4260 ; R6.2@3960,3249.2 R6.2@3960,3230 3997.1,3230 4061.4,3165.6 4061.4,2867 ; 4052.8,2726.7 4052.8,2858.4 4061.4,2867 ; 4177.1,4430 4396.3,4210.8 4530.9,4210.8 D1.1@4580.1,4260 ; 4177.1,4430 4177.1,4490 4180,4492.9 C17.1@4180,4511.4 ; C17.1@4180,4511.4 C17.1@4180,4520.7
  Top Layer w19.68: U4.9@1650,1860 1710,1800 2190,1800 U4.15@2250,1860 ; U2.9@3330,1860 3260.1,1790 3160,1790 U3.15@3090,1860 3030,1920 2550,1920 U3.9@2490,1860 2490,1740 2630,1600 3910,1600 4090,1780 ; U2.15@3930,1860 4000,1780 4090,1780 ; U1.15@4770,1860 4700.2,1790 4240,1790 U1.9@4170,1860 4090,1780
  Top Layer w39.37: LED4.2@4711.3,4100.05 5000,4100 ; 5011.3,4288.2 5000,4276.9 5000,4100 ; CN1.3@5190,3910 5000,4100
  Bottom Layer w9.45: v2(1540,2010) 1540,1970 U4.9@1650,1860 ; H9.2@1660,3100 1611.2,3148.8 1611.2,3251.2 H10.2@1660,3300 ; H14.2@1950,2550 H13.2@1950,2650 H12.2@1950,2750 H11.2@1950,2850 ; U4.15@2250,1860 2303.9,1913.9 2436.1,1913.9 U3.9@2490,1860 ; P1.4@2320,5150 P1.3@2320,5250 ; H23.1@2850,4750 v1(2850,5102.9) ; v1(3263,2037) 3325.3,1974.7 3325.3,1864.7 U2.9@3330,1860 ; v1(3726.3,3915.2) 3726.3,3685.4 v1(3843.3,3568.4) ; v2(4150,2590) v2(4150,2790) ; v2(4240,1950) v2(4240,2090) ; U1.15@4770,1860 4770,1840 H8.2@4960,1650 5149.9,1839.9 H7.2@5301.5,1839.9
  Bottom Layer w78.74: CN1.1@5190,3510 5090,3610 5090,3810 CN1.3@5190,3910
HEATER_BED_PIN: H23.4 U5.26 U9.5 | length 2652.1
  Top Layer w9.45: U5.26@2398,4574 2398,4516.4 2783.6,4516.4 H23.4@2850,4450 ; v1(3553.9,2754.3) 3580,2780.3 U9.5@3580,2802
  Bottom Layer w9.45: H23.4@2850,4450 2801.5,4401.5 2801.5,4022.1 2823.6,4000 2873.1,4000 3553.9,3319.2 v1(3553.9,2754.3)
HEATER_E0_PIN: H23.6 U5.24 U9.12 | length 2580.4
  Top Layer w9.45: U5.24@2511,4446.9 2653.1,4446.9 H23.6@2850,4250 ; U9.12@3680,2558 3680,2520.5 v1(3697.4,2503.2)
  Bottom Layer w9.45: H23.6@2850,4250 3697.4,3402.6 v1(3697.4,2503.2)
IO0: H23.5 Q5.2 U5.25 | length 1453.9
  Top Layer w9.45: U5.25@2448,4574 2755.7,4574 2832,4497.7 2873.7,4497.7 2903.3,4468.1 2903.3,4403.3 H23.5@2850,4350 2902.3,4297.7 2902.3,4095.4 3117.3,3880.3 3312.6,3880.3 Q5.2@3312.6,3919.2
J1_1: J1.1
J1_8: J1.8
J1_9: J1.9
J1_G2: J1.G2
J1_G3: J1.G3
J1_G4: J1.G4
LED1_1: LED1.1 R4.2 | length 110.3
  Top Layer w9.45: R4.2@3789.99,3550.04 3790,3593.3 3790.7,3594 LED1.1@3790.7,3660.05
LED2_1: LED2.1 R15.2 | length 293.8
  Top Layer w9.45: v1(3629.3,4278.1) 3635,4278.1 3636.8,4280 R15.2@3680,4280 ; LED2.1@3680.1,4429.3 3721.9,4429.3 3723.3,4427.9 v1(3730.2,4427.9)
  Bottom Layer w9.45: v1(3629.3,4278.1) 3730.2,4379 v1(3730.2,4427.9)
LED3_1: LED3.1 R13.2 | length 98.6
  Top Layer w9.45: R13.2@4830,4330 4888.7,4330 LED3.1@4928.6,4330.05
LED4_1: LED4.1 R14.2 | length 98.6
  Top Layer w9.45: R14.2@4530,4100 4588.7,4100 LED4.1@4628.6,4100.05
LED5_1: LED5.1 R3.2 | length 110.4
  Top Layer w9.45: R3.2@4720,3060 4787.5,3060 4788.2,3059.3 LED5.1@4830.1,3059.3
LED5_2: CN2.1 LED5.2 Q1.2 | length 1569.8
  Top Layer w9.45: Q1.2@4492.6,3489.9 Q1.2@4580.4,3489.9 ; v1(4540,3752) 4540,3530.3 Q1.2@4580.4,3489.9 ; LED5.2@4830.1,3142 4871.9,3142 4906.5,3176.7 ; 4961.7,3176.7 4906.5,3176.7 ; Q1.2@4580.4,3489.9 4698.8,3489.9 4698.8,3437.2 4712,3424 4906.5,3229.5 4906.5,3176.7
  Top Layer w78.74: 4961.7,3176.7 5088.3,3050 CN2.1@5200,3050
  Bottom Layer w9.45: 4540,3503.3 v1(4540,3752)
LED6_1: LED6.1 R1.2 | length 123.5
  Top Layer w9.45: R1.2@4840,2640 4840,2709.4 4850.1,2719.4 LED6.1@4850.1,2759.3
LED7_1: LED7.1 R2.2 | length 110.3
  Top Layer w9.45: R2.2@4990.1,2270 5057.5,2270 5058.2,2269.3 LED7.1@5100.1,2269.3
LED7_2: H19.2 LED7.2 Q3.4 | length 1580.2
  Top Layer w9.45: Q3.4@4522.7,2590 4664.9,2590 4664.9,2576.9 v1(4722.1,2519.6) ; LED7.2@5100.1,2352 5100.1,2312.1 5132.3,2312.1 5301.5,2142.9 H19.2@5301.5,2139.9
  Bottom Layer w9.45: 4455,2550 4714.3,2550 4714.3,2527.5 v1(4722.1,2519.6) 4921.8,2519.6 H19.2@5301.5,2139.9
MISO: H1.6 J1.3 JP4.1 JP8.1 JP12.1 JP16.1 U5.31 | length 8658.5
  Top Layer w9.45: U5.31@2147.9,4573.9 2147.9,4847.9 H1.6@2150,4850 2240,4940 v2(3370,4940) ; v1(2225.6,4779.9) 2253,4779.9 2300,4826.9 2300,4862.6 2306.7,4869.3 ; v1(2513.5,1939.9) 2509.9,1939.9 2570,2000 2744.7,2000 JP8.1@2790,2000 2835.3,2000 2835.3,1966 2846.6,1954.7 3097.4,1954.7 3131.1,1921.1 v1(3351.5,1921.1) ; J1.3@3438,4791 3438,4858 v2(3440,4860)
  Bottom Layer w9.45: v1(2225.6,4779.9) 2220.1,4779.9 H1.6@2150,4850 2105.6,4894.4 1628.7,4894.4 1592,4857.7 1592,2358 1904.7,2045.3 1950,2045.3 JP4.1@1950,2000 1972.6,2000 1995.3,2000 1995.3,2033.9 2008.9,2047.6 2405.8,2047.6 v1(2513.5,1939.9) ; v1(3351.5,1921.1) 3388.2,1884.4 3388.2,1842.6 3417.8,1813 3447.4,1813 3482.2,1847.7 3482.2,1897.4 3584.7,2000 JP12.1@3630,2000 3652.6,2000 3675.3,2000 3675.3,1966.1 3712.7,1928.6 4042.3,1928.6 4154.4,1816.5 4287.2,1816.5 4320,1849.4 4320,1895.3 4434.7,2010 JP16.1@4480,2010 ; v2(3370,4940) 3370,4930 v2(3440,4860)
MOS_EN: H21.2 U9.4 U9.10 U9.13 | length 1216.6
  Top Layer w9.45: U9.10@3580,2558 3580,2570.4 3617.7,2608.1 3690.9,2608.1 U9.13@3725.1,2573.9 ; U9.4@3630,2802 3630,2814.4 3719.1,2903.5 3843.5,2903.5 H21.2@3940,3000 ; U9.13@3730,2558 3730,2569 U9.13@3725.1,2573.9 ; v1(3940,2623.3) 3774.5,2623.3 U9.13@3725.1,2573.9
  Bottom Layer w9.45: v1(3940,2623.3) H21.2@3940,3000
